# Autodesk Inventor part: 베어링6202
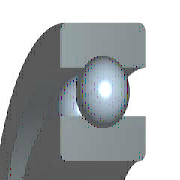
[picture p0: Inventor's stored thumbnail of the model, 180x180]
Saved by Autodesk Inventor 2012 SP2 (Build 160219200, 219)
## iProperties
IsCustomPart: 0
Company: 한국ATC센터
Created: 2014-12
Part Number: 베어링6202
Material: 강, 연강
Description: 깊은 그루브 볼 베어링
Document SubType Name: Modeling
Standard: KS B 2023
Designer: KYOUNG IL JANG
Standards Organization: KS
Language: ko-KR
Size Designation: 6202 - 15 x 35 x 11
Categories: <MemberInstance><Categories><Category DisplayName="샤프트 부품" InternalName="7f7aeb1f-a693-4053-b835-cee3144e0d98" Mnemonic="SHFT"><Category DisplayName="베어링" Inter
Density: 7.86 g/cm^3
Mass: 45.8725 g
Surface Area: 51.5584 cm^2
Volume: 5.83619 cm^3
Author: KYOUNG IL JANG
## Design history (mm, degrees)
revolve "본체" stored, may be unused: angle "d6" = 90 deg
revolve "볼" stored, may be unused: angle "d7" = 90 deg
pattern_circular "IDS_ARRAYBALL[SIMPL:T]" dims angle "d3" = 360 deg
body "Solid1"
sketch "스케치" dims "d0" = 5.2 (= -0.26 x WD + 0.26 x BD)
  geometry: L1 (2.9, 12.5)-(8.1, 12.5); L2 (5.5, 12.5)-(5.5, 9.9); L3 (5.5, 12.5)-(5.5, 15.1); L4 (3.568, 10.76)-(0, 10.76); L5 (0, 7.5)-(11, 7.5); L6 (3.568, 14.24)-(0, 14.24); L7 (0, 17.5)-(11, 17.5); L8 (11, 7.5)-(11, 10.76); L9 (7.432, 10.76)-(11, 10.76); L10 (7.432, 14.24)-(11, 14.24); L11 (11, 17.5)-(11, 14.24); L12 (-1.4, 0)-(8.4, 0) reference; L13 (0, -0.3)-(0, 5.3) reference
  constraints: 22 end point, 4 point on line, 2 collinear, 2 perpendicular, 2 symmetric about line, 1 midpoint, 1 parallel, 14 other
  dimensions: "d9" = 15 diameter of L5 L12 (= WD); "d11" = 35 diameter of L7 L12 (= BD); "d12" = 11 distance between parallel lines of L8 L13 (= KB); "d13" = 21.52 diameter of L9 L12 (= 0.326 x BD + 0.674 x WD)
fillet "모깎기1" dims "d1" = 0.6 (= KRS)
other parameters: "WD" = 15 [user parameter; used in 5 equation terms], "BD" = 35 [user parameter; used in 5 equation terms], "KB" = 11 [user parameter; used in 1 equation term], "KRS" = 0.6 [user parameter; used in 1 equation term], "d4" = 0, "d5" = 0, "d8" = 0, "d14" = 0, "d15" = 0, "BBA" = 0 [user parameter], "BC0" = 3750000 [user parameter], "BC" = 7800000 [user parameter], "BR" = 17.5 (= 0.5 x BD) [user parameter], "WR" = 7.5 (= 0.5 x WD) [user parameter]
